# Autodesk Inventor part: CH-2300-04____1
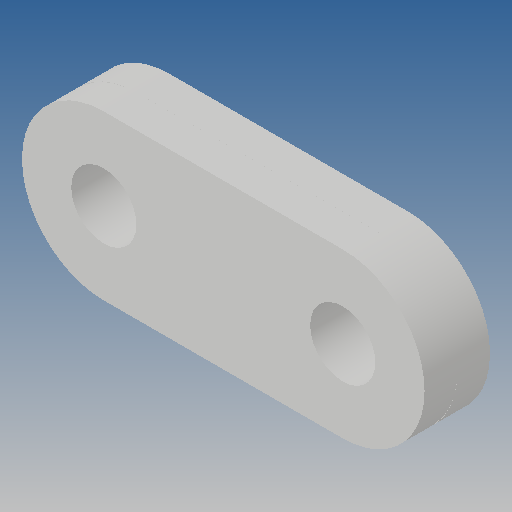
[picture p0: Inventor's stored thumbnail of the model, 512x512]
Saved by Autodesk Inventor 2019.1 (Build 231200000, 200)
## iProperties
Created: 2012-09
Part Number: CH-2300-04____1
Material: Ogólny
Document SubType Name: Modeling
Designer: CADENGINEERING4
Density: 1 g/cm^3
Appearance: Domyślna
Author: CADENGINEERING4
Revision Number: ÈÎºÎ
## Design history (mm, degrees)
feature "NONE" [ÊäÈë]
feature "ÊäÈë2"
node "Bryła1"
node "Bryła2"
